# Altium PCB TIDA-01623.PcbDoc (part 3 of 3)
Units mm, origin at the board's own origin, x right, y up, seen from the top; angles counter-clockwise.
Board outline 77.73 x 42 mm, 4 copper layers (Top Layer, Signal Layer 1, Signal Layer 2, Bottom Layer), stack 0.651 mm thick; 213 components, 127 nets, 575 pads, 342 vias.
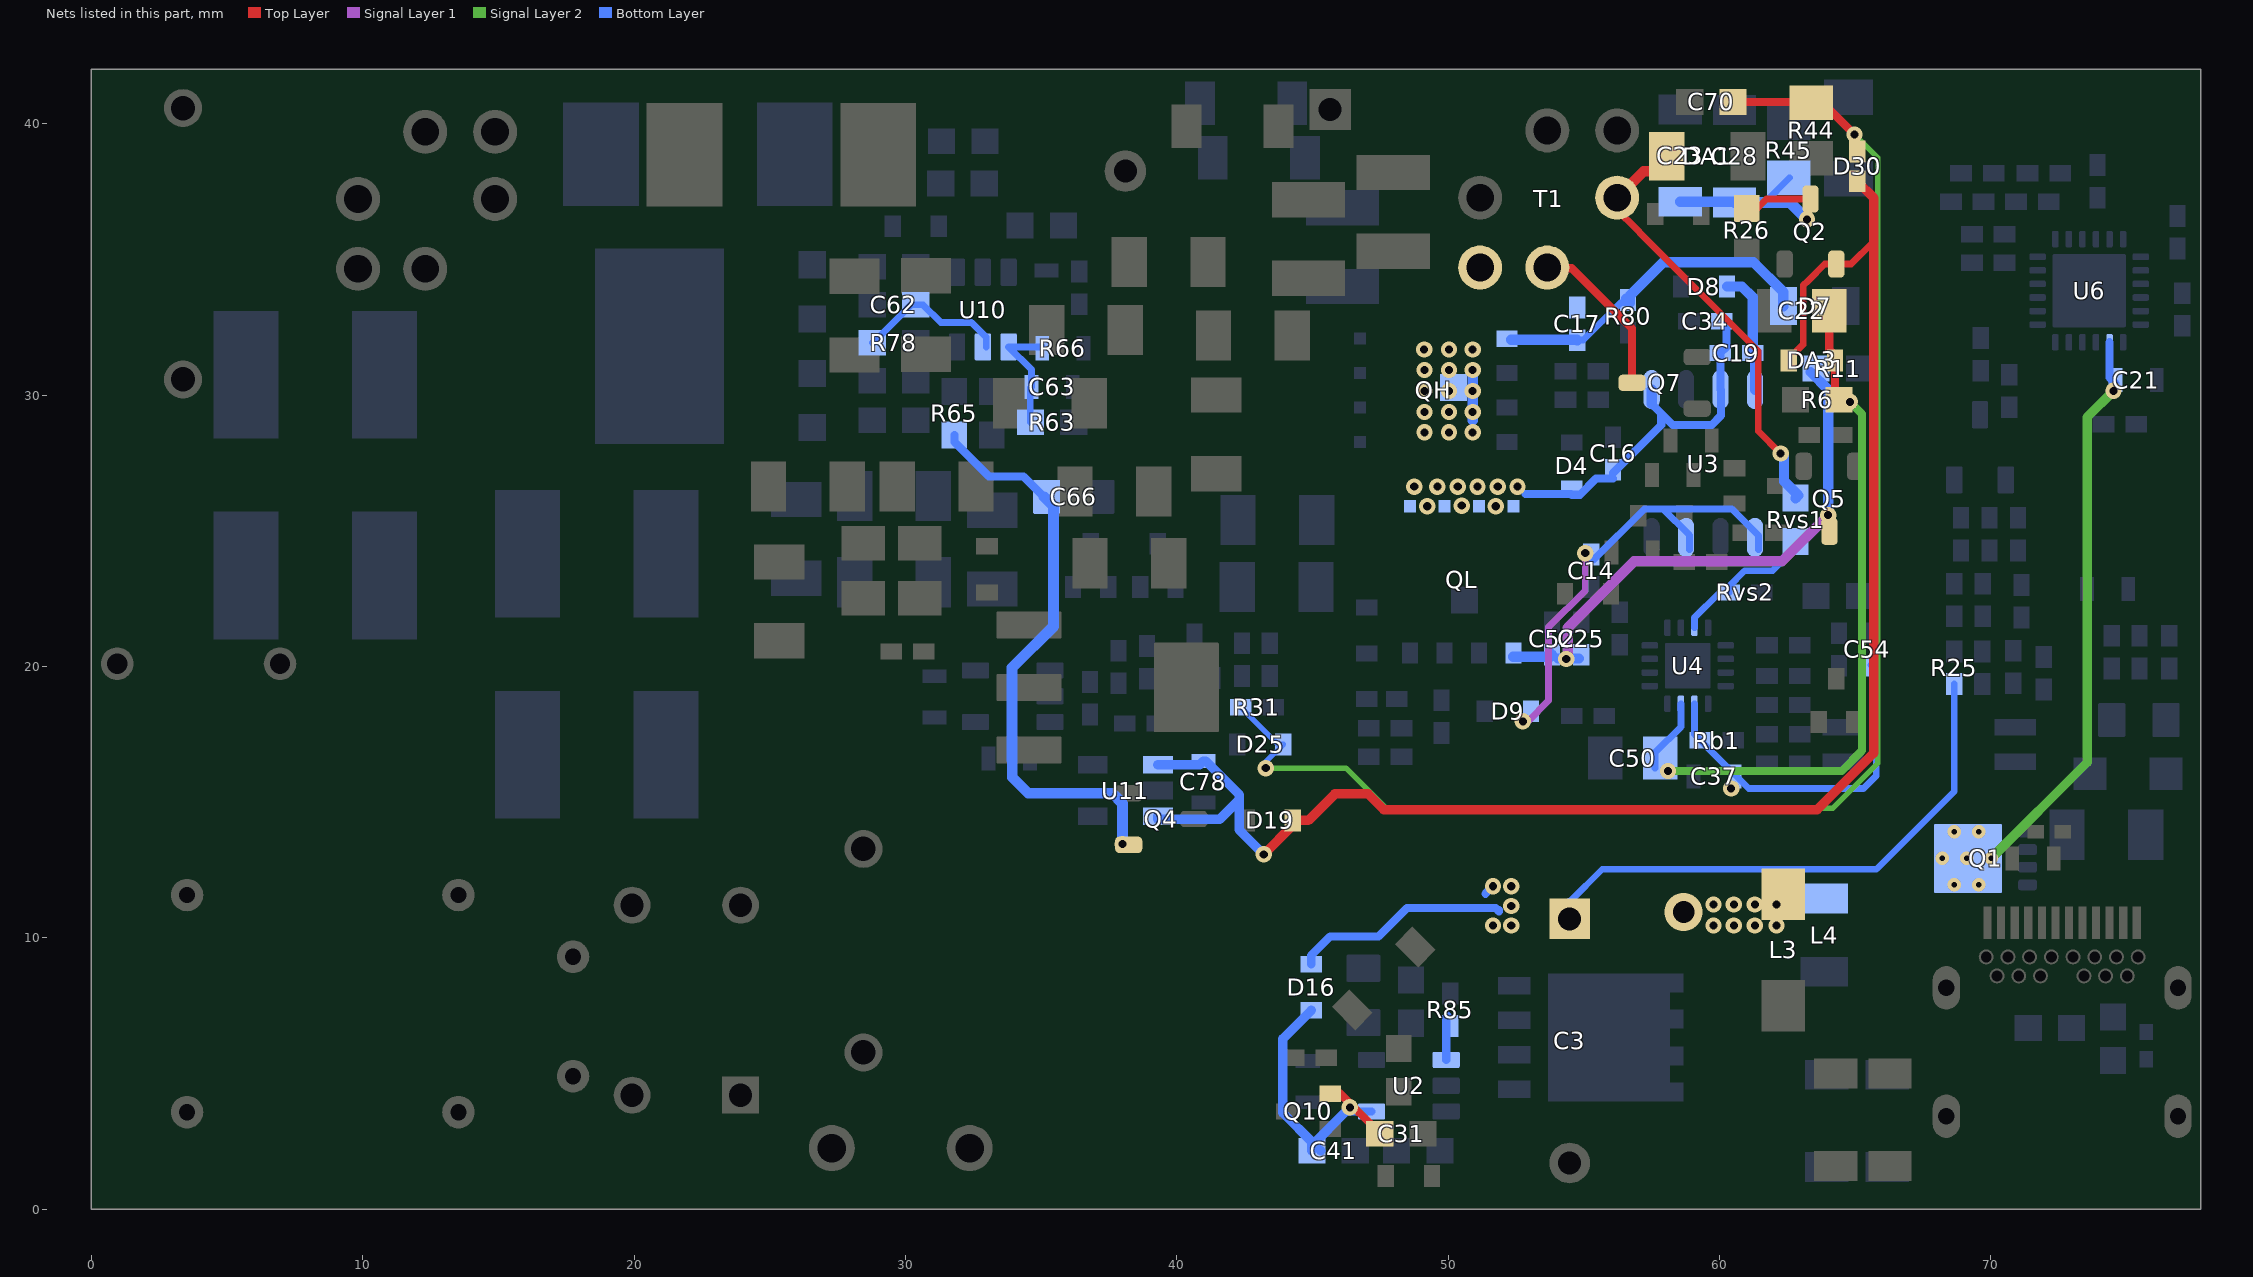
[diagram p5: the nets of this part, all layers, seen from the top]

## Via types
v1: diameter 0.6, hole 0.3, Top Layer to Bottom Layer, 299 vias
v2: diameter 0.635, hole 0.33, Top Layer to Bottom Layer, 15 vias
v3: diameter 0.5, hole 0.2, Top Layer to Bottom Layer, 12 vias
v4: diameter 0.61, hole 0.305, Top Layer to Bottom Layer, 5 vias
v5: diameter 1, hole 0.6, Top Layer to Bottom Layer, 2 vias
v6: diameter 2.4, hole 1.8, Top Layer to Bottom Layer, 2 vias
v7: diameter 1.2, hole 0.8, Top Layer to Bottom Layer, 2 vias
v8: diameter 1.4, hole 0.8, Top Layer to Bottom Layer, 2 vias
v9: diameter 2, hole 1.6, Top Layer to Bottom Layer, 1 vias
v10: diameter 1.9, hole 1.5, Top Layer to Bottom Layer, 1 vias
v11: diameter 0.6/0.6/0.6/0.6 (per signal layer), hole 0.3, Top Layer to Bottom Layer, 1 vias

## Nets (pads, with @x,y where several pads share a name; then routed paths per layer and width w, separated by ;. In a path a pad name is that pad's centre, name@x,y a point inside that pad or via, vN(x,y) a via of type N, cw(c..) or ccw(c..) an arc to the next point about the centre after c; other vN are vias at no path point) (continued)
VCC1: C14.1 D9.2 U3.1 U3.3 | length 17.4
  Signal Layer 1 w0.254: v1(52.75,17.975) 52.933,17.975 53.7,18.742 53.7,21.45 55.05,22.8 v1(55.05,24.175)
  Bottom Layer w0.254: v1(55.05,24.175) 55.074,24.175 55.337,23.912 57.227,25.802 57.923,25.802 58.89,24.835 U3.3@58.89,24.3 ; 57.925,25.8 59.773,25.8 59.775,25.802 60.295,25.802 60.297,25.8 60.45,25.8 61.43,24.82 U3.1@61.43,24.3
VCC2: C19.1 D8.2 U3.8 | length 4.5
  Bottom Layer w0.381: D8.2@60.275,34 60.825,34 61.222,33.603 C19.1@61.222,31.549 61.305,31.466 U3.8@61.305,30.2
VCC_PFC: C66.1 Q4.2 R65.2 | length 22
  Top Layer w0.3: v1(38,13.45) 38.475,13.45 Q4.2@38.5,13.425
  Bottom Layer w0.3: R65.2@31.8,28.525 31.8,28.275 33.075,27 34.35,27 C66.1@35.1,26.25
  Bottom Layer w0.4: C66.1@35.1,26.25 35.45,25.9 35.45,21.475 33.925,19.95 33.925,16.547 33.933,16.539 33.933,15.917 34.525,15.325 37.625,15.325 38,14.95 v1(38,13.45)
VCCH: C17.1 D7.1 QH.1 R80.2 | length 12.6
  Bottom Layer w0.25: C17.1@54.75,32.025 54.975,32.025 56.35,33.4 R80.2@56.7,33.4
  Bottom Layer w0.381: QH.1@52.328,32.038 54.737,32.038 C17.1@54.75,32.025 ; R80.2@56.55,33.55 56.613,33.488 56.7,33.4 56.7,33.675 57.925,34.9 61.25,34.9 62.35,33.8 D7.1@62.35,33.275
VCCL: C25.1 C52.1 Q5.3 QL.1 R11.2 | length 20.2
  Signal Layer 1 w0.381: v1@54.4,20.3 54.4,21.418 55.567,22.586 55.567,22.592 56.85,23.875 62.3,23.875 v1(64,25.575)
  Bottom Layer w0.381: QL.1@52.394,20.362 C52.1@53.762,20.362 ; C52.1@53.763,20.487 C52.1@53.825,20.425 ; C52.1@54.05,20.294 C25.1@54.819,20.294 ; R11.2@63.35,30.85 64,30.2 v1(64,25.575)
  other v1: 54.35,20.275
VDD: C22.1 C50.1 DA3.1 R6.1 U4.15 | length 26.1
  Top Layer w0.3: C22.1@64.041,33.125 64.041,31.684 DA3.1@64.325,31.4 ; DA3.1@64.25,31.325 64.25,29.975 R6.1@64.4,29.825
  Signal Layer 2 w0.3: v1@58.375,16.15 64.5,16.15 65.25,16.9 65.25,29.3 v1@64.975,29.575
  Bottom Layer w0.25: C50.1@57.625,16.25 57.625,16.825 58.575,17.775 U4.15@58.575,18.625
  other v1: 58.1,16.15 64.8,29.75
VDD1: C23.1 C28.1 Q2.3 R26.2 R45.1 | length 9
  Top Layer w0.25: R26.2@61.375,36.875 61.725,37.225 63.2,37.225 63.225,37.2 v1(63.225,36.475)
  Bottom Layer w0.25: C28.1@60.525,37.125 C28.1@60.55,37.1 ; 61.666,37.1 R45.1@62.575,38.009
  Bottom Layer w0.4: C23.1@58.55,37.125 C28.1@60.525,37.125 ; C28.1@60.55,37.1 61.666,37.1 62.6,37.1 v1(63.225,36.475)
VDD2: C70.1 D25.1 D30.2 R31.1 R44.1 | length 55.2
  Top Layer w0.3: C70.1@60.5,40.8 R44.1@63.341,40.8 ; R44.1@63.809,40.766 v1(64.975,39.6)
  Signal Layer 2 w0.2: v1(43.275,16.25) 46.225,16.25 47.7,14.775 64.175,14.775 65.825,16.425 65.825,38.75 v1(64.975,39.6)
  Bottom Layer w0.2: R31.1@42.35,18.5 43.725,17.125 D25.1@43.925,17.125 43.275,16.475 v1(43.275,16.25)
VDD3: C78.2 D19.2 D30.1 DA3.2 Q2.2 U11.1 U11.3 | length 61.5
  Top Layer w0.25: DA3.2@62.55,31.325 63.081,31.856 63.081,34.035 63.271,34.225 63.275,34.225 63.875,34.825 Q2.2@64.15,34.825 ; Q2.2@64.3,34.825 64.85,34.825 65.675,35.65
  Top Layer w0.35: v1(43.2,13.075) 44.275,14.15 D19.2@44.275,14.325 44.85,14.325 45.825,15.3 47.054,15.3 47.625,14.729 47.625,14.725 63.6,14.725 65.675,16.8 65.675,35.65 65.675,37.275 D30.1@65.075,37.875
  Bottom Layer w0.35: U11.3@39.3,14.475 39.3,14.359 41.575,14.359 42.291,15.075 42.3,15.075 ; U11.1@39.3,16.375 40.838,16.375 C78.2@40.975,16.512 41.063,16.512 42.3,15.275 42.3,15.075 ; v1(43.2,13.075) 42.3,13.975 42.3,15.075
VDDS: C31.1 C41.2 D16.1 Q10.2 U2.4 | length 11.8
  Top Layer w0.3: Q10.2@45.65,4.25 46.025,4.25 47.475,2.8 C31.1@47.475,2.775
  Bottom Layer w0.3: v1@46.225,3.6 U2.4@47.175,3.6
  Bottom Layer w0.35: D16.1@44.95,7.325 43.9,6.275 43.9,3.55 45.037,2.412 45.137,2.312 C41.2@45.3,2.15 ; C41.2@44.975,2.15 44.975,2.35 46.225,3.6 v1(46.375,3.75)
VG: R85.2 U2.1 | length 1.6
  Bottom Layer w0.3: U2.1@49.925,5.5 49.925,7.075 R85.2@49.975,7.125
VO: C3.1 C21.1 D16.2 L3.2 L4.2 Q1.5 Q1.6 Q1.7 Q1.8 Q1.9@69.155,12.925 R25.2 U6.20 | length 49.2
  Signal Layer 2 w0.25: v1@74.354,30.154 v1(74.517,30.154)
  Signal Layer 2 w0.35: v3(70.008,12.925) 73.55,16.468 73.55,29.187 v1(74.517,30.154)
  Bottom Layer w0.25: C3.1@54.45,11.35 54.5,11.35 55.675,12.525 65.534,12.525 65.775,12.525 68.65,15.4 R25.2@68.65,19.35
  Bottom Layer w0.3: D16.2@44.95,9.025 44.95,9.35 45.65,10.05 47.425,10.05 48.475,11.1 51.75,11.1 51.875,10.975 51.875,11.025 ; 51.375,11.625 v1(51.65,11.9) ; U6.20@74.37,31.945 74.37,30.645 C21.1@74.583,30.432
  other v1: 51.65,10.45 52.325,10.45 59.775,10.45 60.525,10.45 61.3,10.45 62.1,10.45 52.325,11.175 59.775,11.225 60.525,11.225 61.3,11.225 62.1,11.225 52.325,11.9
  other v3: 68.65,11.95 69.555,11.95 68.198,12.925 69.103,12.925 68.65,13.9 69.555,13.9
  other v8: 58.675,10.95
VOSNS: C63.2 R63.1 R66.2 U10.1 | length 4.4
  Bottom Layer w0.25: R63.1@34.6,29 34.6,30.262 C63.2@34.638,30.3 34.638,30.937 U10.1@33.8,31.775 R66.2@35.038,31.775
VREF: C37.1 C54.1 Rb1.2 U4.14 | length 13
  Bottom Layer w0.25: U4.14@59.075,18.625 59.075,17.5 Rb1.2@59.3,17.275 61.075,15.5 65.3,15.5 65.775,15.975 65.775,19.85 C54.1@65.575,20.05
  other v1: 60.425,15.5
VS: Rvs1.1 Rvs2.2 U4.7 | length 5
  Bottom Layer w0.25: U4.7@59.075,21.425 59.075,21.8 59.95,22.675 ; Rvs2.2@60.35,22.725 60.35,22.95 60.925,23.525 61.95,23.525 Rvs1.1@62.875,24.45
VSV: DA1.2 Rvs1.2 T1.3 | length 16.4
  Top Layer w0.25: T1.3@56.225,37.275 56.225,36.825 56.935,36.115 56.935,36.113 57.163,35.884 57.166,35.884 61.425,31.625 61.425,28.675 v1(62.25,27.85)
  Top Layer w0.381: T1.3@56.225,37.275 57.2,38.25 DA1.2@58.3,38.25
  Bottom Layer w0.381: v1(62.25,27.85) 62.375,27.725 62.375,26.825 62.9,26.3 Rvs1.2@62.8,26.2
VSW: C16.2 C17.2 C19.2 C34.1 D4.2 Q7.3 QH.9 QL.5 QL.6 QL.7 QL.8 T1.4 T1.5 U3.5 U3.7 | length 21.4
  Top Layer w0.3: T1.4@53.625,34.675 54.55,34.675 56.775,32.45 Q7.3@56.775,30.375
  Bottom Layer w0.3: 52.85,26.35 54.525,26.35 54.55,26.325 54.85,26.325 55.45,26.925 C16.2@56.075,26.925 ; C16.2@56.075,27.125 57.85,28.9 57.85,29.325 ; U3.5@57.495,29.68 57.85,29.325 ; C34.1@60.25,32.675 60.25,31.777 C19.2@60.022,31.549 60.035,31.536 U3.7@60.035,30.2 60.05,30.185 60.05,29.24 59.71,28.9 58.275,28.9 57.85,29.325
  Bottom Layer w0.381: v1@50.9,29.075 v1@50.9,30.8 ; U3.5@57.495,29.68 U3.5@57.495,30.2
  other v1: 49.225,25.9 51.75,25.9 50.5,25.925 48.75,26.625 49.6,26.625 50.35,26.625 51.075,26.625 51.825,26.625 52.55,26.625 49.125,28.625 50.025,28.625 50.9,28.625 49.125,29.375 50.025,29.375 50.9,29.375 49.125,30.15 50.025,30.15 50.9,30.15 49.125,30.925 50.025,30.925 50.9,30.925 49.111,31.675 50.025,31.675 50.9,31.675
ZCD: C62.2 R78.1 U10.2 | length 5.6
  Bottom Layer w0.25: R78.1@28.775,31.925 28.81,31.925 30.21,33.325 C62.2@30.375,33.325 30.65,33.325 31.3,32.675 32.425,32.675 32.979,32.121 U10.2@32.979,31.771
pads on no net: J2.A2 J2.A3 J2.A8 J2.A10 J2.A11 J2.B2 J2.B3 J2.B8 J2.B10 J2.B11 Q1.9@68.625,11.95 Q1.9@68.625,12.6 Q1.9@68.625,13.9 Q1.9@68.625,13.25 Q1.9@69.103,12.263 Q1.9@69.103,13.587 Q1.9@69.473,12.925 Q1.9@70.008,12.263 Q1.9@70.008,13.587 U4.17@58.825,20.025 U6.9 U6.10 U6.25@72.925,33.15 U6.25@72.925,34.54 U6.25@74.315,33.15 U6.25@74.315,34.54 U11.4

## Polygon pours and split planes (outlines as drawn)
SGND on Bottom Layer "Signal Layer 2-No Net 3" (solid, pour order 378): 68.151,9.676 76.949,9.676 77.575,9.05 77.575,0.575 77.25,0.25 67.825,0.25 66.25,0.25 65.5,1 65.5,7.025
390V_BUS on Bottom Layer "Bottom Layer-No Net 11" (solid, pour order 242): 43.6,41.625 49.925,41.625 50.75,40.8 50.75,39.05 50.75,39.025 52.05,37.725 52.025,37.7 52.025,36.825 51.725,36.525 48.225,36.525 47.9,36.2 46.675,36.2 43.925,36.2 43.475,36.65 43.475,41.5
DRAIN on Bottom Layer "Bottom Layer-No Net 9" (solid, pour order 230): 11.925,41.525 20.85,41.525 21.925,40.45 21.925,37.375 24.4,34.9 24.4,28.4 24.15,28.15 18.6,28.15 15.45,31.3 15.45,35.555 11.425,39.448 11.425,41.025
GDNS on Bottom Layer "Bottom Layer-No Net 7" (solid, pour order 184): 71.1,15.125 73.375,15.125 73.65,14.85 73.65,12.975 73.475,12.8 72.025,12.8 71.625,12.4 71,12.4 70.875,12.525 70.875,14.9
VO on Bottom Layer "Top Layer-No Net 2" (solid, pour order 182): 51.075,10.325 51.5,9.9 69.875,9.9 70.5,10.525 70.5,14.5 68.275,14.5 66,12.225 63.15,12.225 55.253,12.225 54.903,12.45 51.2,12.45 51.075,12.325
PGND on Bottom Layer "Bottom Layer-No Net 4" (solid, pour order 172): 43.3,21.9 43.3,27.3 42.3,28.3 42.3,40.75 41.425,41.625 39.875,41.625 36.925,41.625 36.1,40.8 36.1,38.8 38.6,36.3 38.6,26.475 40.8,24.275 40.8,22.2 41.1,21.9
F on Bottom Layer "Top Layer-No Net" (solid, pour order 158): 53.695,9.345 61.854,9.345 62.255,8.945 62.254,4.629 61.45,3.825 60.6,3.825 60.53,3.895 53.755,3.895 53.475,4.175 53.475,9.125
VBUS on Bottom Layer "Bottom Layer-No Net 2" (solid, pour order 150): 75.05,14.75 77.225,14.75 77.7,14.275 77.55,14.125 77.55,10.95 77.55,9.7 75.83,9.7 75.055,8.925 70.644,8.925 70.644,10.844 71.275,11.475 72.675,11.475 74.85,13.65 74.85,14.55
PGND1 on Bottom Layer "Bottom Layer-No Net 1" (solid, pour order 138): 43.6,26.6 46.825,26.6 46.825,24.9 47.875,23.85 54.325,23.85 55.6,22.575 55.6,21.575 55.2,21.175 44.575,21.175 43.6,22.15
SGND on Bottom Layer "Bottom Layer-No Net 5" (solid, pour order 176): 53.5,3.5 62.325,3.5 62.975,4.15 67.175,4.15 67.175,0.275 60.875,0.275 56.9,0.275 51.175,0.275 50.7,0.75 50.7,7.125 51.2,7.625 52.925,7.625 53.184,7.366 53.184,3.816
AC_R on Bottom Layer "Bottom Layer-No Net 14" (solid, pour order 268): 8.775,37.55 9.325,38.1 10.15,38.1 13.337,34.913 13.337,30.72 17.6,26.178 17.6,21.875 17.275,21.55 14.875,21.55 14.65,21.775 14.65,26.1 12.575,28.175 9.675,28.175 9.4,28.45 9.4,34.05 8.775,34.675
VSW on Bottom Layer "Bottom Layer-No Net" (solid, pour order 110): 55.154,35.5 55.725,34.979 55.725,33.425 55.05,32.75 51.65,32.75 51.45,32.55 51.45,27.8 51.55,27.7 56.4,27.7 56.6,27.5 56.6,26.925 55.35,25.675 54.575,25.675 53.95,25.05 48.25,25.05 47.925,25.375 47.925,27.125 48.5,27.7 48.5,31.925 49.4,32.825 49.4,34.825 50.075,35.5
NetC42_1 on Bottom Layer "Bottom Layer-No Net 3" (solid, pour order 170): 47.075,27.75 47.3,27.975 47.3,32.325 48.3,33.325 48.3,35.375 48.05,35.625 43.7,35.625 43.45,35.375 43.45,29.025 44.725,27.75
390V_BUS on Bottom Layer "Bottom Layer-No Net 12" (solid, pour order 306): 24.15,41.4 28.175,41.4 28.175,38.1 26.875,36.8 24.575,36.8 23.925,37.45 23.925,41.175
SGND on Bottom Layer "Bottom Layer-No Net 16" (solid, pour order 316): 74.025,18.95 74.8,18.95 74.8,18.925 75.025,18.7 75.025,15.875 74.575,15.425 74.1,15.425 72.925,15.425 72.8,15.55 72.825,15.575 72.825,16.55 72.825,16.6 73.1,16.875 73.675,17.45 73.675,17.625 73.675,18.6
PGND on Bottom Layer "Bottom Layer-No Net 17" (solid, pour order 318): 58,19.45 56.225,19.45 56.05,19.45 55.225,18.625 55.2,18.6 55.2,17.625 55.075,17.5 54.175,17.5 53.85,17.175 53.85,15.408 54.386,15 59.625,15 59.8,15.175 59.8,16.25 59.5,16.55 58.85,16.55 58.825,16.55 58.625,16.35 58.1,15.825 57,15.825 57,17.675 58,17.675 58.375,18.05 58.375,19.325 58.25,19.45 58.2,19.5 58.05,19.5
S on Bottom Layer "Bottom Layer-No Net 15" (solid, pour order 320): 63,9.475 66.9,9.475 67.35,9.025 67.35,4.7 66.975,4.325 66.825,4.325 63.025,4.325 62.875,4.475 62.875,5.775 62.875,9.35
PGND on Bottom Layer "Top Layer-No Net 8" (solid, pour order 322): 0.75,33.725 6.475,33.725 7.025,33.175 7.025,28.4 6.725,28.1 0.875,28.1 0.35,28.625 0.35,33.325
NetBD1_2 on Bottom Layer "Bottom Layer-No Net 13" (solid, pour order 324): 4.45,25.825 11.625,25.825 11.9,25.825 12.125,25.6 12.125,20.175 11.375,19.425 5.5,19.425 4.875,19.425 4.325,19.975 4.325,25.7
NetBD2_2 on Bottom Layer "Bottom Layer-No Net 18" (solid, pour order 326): 14.9,19.3 22.25,19.3 22.475,19.3 22.725,19.05 22.725,14.65 22.425,14.35 17.15,14.35 13.725,10.925 12.35,10.925 12.1,10.925 11.45,11.575 11.45,14.825 11.45,15.475 14.7,18.725 14.7,19.1
AC_R on Bottom Layer "Bottom Layer-No Net 19" (solid, pour order 336): 1,41.7 0.325,41.025 0.325,37.55 1.6,36.275 6.95,36.275 9.5,33.725 10.775,33.725 12.65,35.6 9.05,39.2 9.05,41.35 8.7,41.7
PGND on Bottom Layer "Bottom Layer-No Net 20" (solid, pour order 348): 20,26.525 22.35,26.525 22.425,26.45 22.425,21.825 22.375,21.775 20,21.775 19.925,21.85 19.925,26.45 20,26.525
NetC57_2 on Bottom Layer "Bottom Layer-No Net 21" (solid, pour order 358): 26.025,33.3 27.675,33.3 27.85,33.125 27.85,31.375 28.2,31.025 29.25,31.025 29.35,30.925 29.35,28.525 29.125,28.3 26.325,28.3 26.075,28.3 25.95,28.425 25.95,33.225
PGND on Bottom Layer "Bottom Layer-No Net 13" (solid, pour order 366): 29.8,35.425 32,35.425 32.25,35.125 32.25,34.125 32.25,34.075 32.425,33.9 37.4,33.9 37.725,33.575 37.725,25.6 37.3,25.175 32.7,25.175 32.7,28.2 36.903,28.2 37.025,28.322 37.025,29.459 36.707,29.776 35.926,29.776 35.693,30.009 35.693,32.307 35.55,32.45 33.3,32.45 32.65,33.1 31.775,33.1 31.75,33.1 31.475,33.375 31.275,33.575 31.275,34.15 31.2,34.225 29.8,34.225
SGND on Top Layer "Signal Layer 2-No Net 3" (solid, pour order 376): 67.4,11.275 77.325,11.275 77.575,11.025 77.575,0.575 77.25,0.25 67.825,0.25 65.777,0.25 65.5,0.527 65.5,9.375
PGND on Top Layer "Top Layer-No Net 4" (solid, pour order 250): 36.6,41.625 40.575,41.625 40.675,41.625 41.175,41.125 41.2,41.1 41.2,38.025 41.2,37.95 40.925,37.675 40.775,37.525 36.4,37.525 32.525,33.65 27.075,33.65 26.825,33.9 26.825,35.4 27.1,35.675 31.125,35.675 32.45,37 32.45,40.9 33.175,41.625
390V_BUS on Top Layer "Bottom Layer-No Net 12" (solid, pour order 248): 26.2,41.65 30.4,41.65 30.4,37.35 29.975,36.925 26.225,36.925 25.975,37.175 25.975,41.425
390V_BUS on Top Layer "Bottom Layer-No Net 11" (solid, pour order 244): 44,41.625 49.925,41.625 50.75,40.8 50.75,39.05 50.75,39.025 52.05,37.725 52.025,37.7 52.025,36.85 51.65,36.475 51.625,36.45 50.575,36.45 50.3,36.45 49.7,37.05 46.7,37.05 46.2,36.55 43.475,36.55 43.25,36.775 43.25,40.875
SGND on Top Layer "Bottom Layer-No Net 5" (solid, pour order 178): 49.125,4.175 52.425,4.175 53.225,3.375 61.636,3.375 65.925,3.375 65.925,0.675 65.475,0.225 48.95,0.225 48.55,0.625 48.55,3.6
VO on Top Layer "Top Layer-No Net 2" (solid, pour order 166): 51.325,9.875 52,9.2 68.439,9.2 70.25,12 70.25,14.175 67.375,14.175 65.825,12.625 51.925,12.625 51.325,12.025
S on Top Layer "Top Layer-No Net 1" (solid, pour order 164): 63.35,3.575 66.775,3.575 67.525,4.325 67.525,7.825 66.575,8.775 61.775,8.775 61.5,8.5 61.5,6.6 62.875,5.225 62.875,4.05
F on Top Layer "Top Layer-No Net" (solid, pour order 156): 50.25,8.9 60.975,8.9 61.175,8.7 61.175,6.4 62.1,5.475 62.1,4.425 61.45,3.775 53.525,3.775 52.725,4.575 50.431,4.575 49.875,5.131 49.875,8.525
SGND on Top Layer "Signal Layer 2-No Net 2" (solid, pour order 154): 76.2,38.725 77.725,37.2 77.725,12.45 70.65,12.45 68.275,14.825 68.275,36.6 70.4,38.725
NetC42_1 on Top Layer "Bottom Layer-No Net 3" (solid, pour order 192): 46.85,27.95 47.3,28.4 47.3,32.625 49.325,34.65 49.325,35.875 49.25,35.95 43.675,35.95 43.425,35.7 43.425,28.35 43.825,27.95
NetC57_2 on Top Layer "Top Layer-No Net 5" (solid, pour order 270): 26.125,32.225 31.825,32.225 31.96,32.09 31.96,29.66 31.125,28.825 26.25,28.825 26.125,28.95
PGND on Top Layer "Top Layer-No Net 6" (solid, pour order 276): 41.85,25.025 42.9,25.025 43.075,24.85 43.075,22.975 42.8,22.7 42.025,22.7 41.7,23.025 41.7,24.875
VSW on Top Layer "Bottom Layer-No Net" (solid, pour order 280): 54.225,35.5 55.175,34.55 55.175,29.225 55.175,25.85 54.35,25.025 48.25,25.025 47.925,25.35 47.925,27.1 48.675,27.85 48.675,32.225 50.325,33.875 50.325,35 50.825,35.5
PGND on Top Layer "Signal Layer 2-No Net" (solid, pour order 284): 60.133,15.25 60.958,15.925 62.45,15.925 63.05,16.525 63.05,21.493 60.556,21.493 54.381,21.493 53.456,20.568 44.225,20.568 44.225,15.25
PGND1 on Top Layer "Bottom Layer-No Net 1" (solid, pour order 310): 43.45,26.6 46.825,26.6 46.825,24.9 47.875,23.85 53.175,23.85 53.65,23.375 53.75,23.275 53.75,21.875 53.275,21.4 44.25,21.4 43.45,22.2
PGND on Top Layer "Top Layer-No Net 8" (solid, pour order 328): 0.75,33.725 6.475,33.725 7.025,33.175 7.025,28.4 6.725,28.1 0.875,28.1 0.35,28.625 0.35,33.325
NetBD1_2 on Top Layer "Bottom Layer-No Net 13" (solid, pour order 330): 4.45,25.825 11.625,25.825 11.9,25.825 12.125,25.6 12.125,20.175 11.375,19.425 5.5,19.425 4.875,19.425 4.325,19.975 4.325,25.7
AC_R on Top Layer "Bottom Layer-No Net 10" (solid, pour order 234): 13,35.025 16.425,35.025 18.075,36.675 18.075,41.6 23,41.6 23.625,41.6 23.625,29.775 22.125,28.275 19.7,28.275 16.55,25.125 15.625,25.125 13.15,27.6 13.15,30.045 13,30.239
NetBD2_2 on Top Layer "Bottom Layer-No Net 18" (solid, pour order 338): 14.9,19.3 21.1,19.3 22.725,17.675 22.725,14.725 22.4,14.4 17.2,14.4 13.775,10.975 12.05,10.975 11.45,11.575 11.45,14.825 11.45,15.475 14.7,18.725 14.7,19.1
AC_R on Top Layer "Bottom Layer-No Net 14" (solid, pour order 340): 9.4,38.1 10.15,38.1 13.337,34.913 13.337,30.72 17.6,26.178 17.6,21.875 17.275,21.55 14.875,21.55 14.65,21.775 14.65,26.1 12.575,28.175 9.975,28.175 9.4,28.75 9.4,35.55
AC_R on Top Layer "Bottom Layer-No Net 19" (solid, pour order 342): 1,41.7 0.325,41.025 0.325,37.375 1.325,36.375 6.775,36.375 9.425,33.725 10.025,33.725 12.275,35.975 9.05,39.2 9.05,40.5 7.85,41.7
PGND on Top Layer "Bottom Layer-No Net 20" (solid, pour order 350): 20.325,26.525 22.35,26.525 22.425,26.45 22.425,21.825 22.375,21.775 20,21.775 19.925,21.85 19.925,26.125
SGND on Signal Layer 2 "Signal Layer 2-No Net 3" (solid, pour order 374): 68.55,10.375 77.025,10.375 77.15,10.375 77.55,9.975 77.575,9.95 77.575,0.575 77.25,0.25 67.825,0.25 66.25,0.25 65.125,1.375 65.125,6.95
SGND on Signal Layer 2 "Signal Layer 1-No Net" (solid, pour order 372): 42.95,0.35 67.175,0.35 67.175,2.025 54.5,2.025 52.375,4.15 51.378,4.15 49.575,5.953 49.575,9.725 43.875,9.725 42.275,8.125 42.275,1.025
SGND on Signal Layer 2 "Signal Layer 2-No Net 2" (solid, pour order 302): 77.3,39.475 77.725,39.05 77.725,10.725 68.35,10.725 65.771,8.146 64.85,6.306 64.85,2.725 64.475,2.35 59.866,2.35 56.025,2.35 54.25,2.35 55.325,3.425 61.969,3.425 62.675,4.131 62.675,12.725 65.925,12.725 67.95,14.75 67.95,38.1 69.325,39.475
F on Signal Layer 2 "Top Layer-No Net" (solid, pour order 298): 50.85,9.525 61.7,9.525 62.175,9.05 62.175,4.075 61.8,3.7 52.25,3.7 50.65,5.3 49.9,6.05 49.9,8.575
VO on Signal Layer 2 "Top Layer-No Net 2" (solid, pour order 294): 50.125,10.1 50.3,9.925 62.425,9.925 62.425,12.675 50.475,12.675 50.125,12.325
PGND on Signal Layer 2 "Signal Layer 2-No Net" (solid, remove dead copper, pour order 108): 65.65,21 65.65,41.6 56.25,41.6 56.25,36.425 58.65,34.025 58.65,27.565 56.65,25.565 56.65,24.989 52.31,21.225 45.128,21.225 44.189,21.8 40.625,21.8 40.625,15.25 62.2,15.25 63.425,16.475 63.425,19.725 62.8,20.35 59.6,20.35 59.6,21 63.25,21
NetC42_1 on Signal Layer 2 "Bottom Layer-No Net 3" (solid, pour order 188): 47,27.75 47.3,28.05 47.3,32.15 49.2,34.05 49.2,35.85 48.975,36.075 43.775,36.075 43.525,35.825 43.525,29.875 44.55,28.85 44.55,28.05 44.85,27.75
VSW on Signal Layer 2 "Bottom Layer-No Net" (solid, pour order 200): 54.7,35.575 55.325,34.95 55.325,26.75 53.625,25.05 48.25,25.05 47.925,25.375 47.925,27.125 48.675,27.875 48.675,32.25 50.225,33.8 50.225,35.125 50.675,35.575
PGND on Signal Layer 2 "Bottom Layer-No Net 4" (solid, pour order 256): 43.3,22.4 43.8,22.9 43.8,28.425 42.875,29.35 42.875,37.475 41.35,39 37.925,39 37.45,38.525 37.45,37.6 40.3,34.75 40.3,23.125 41.025,22.4
390V_BUS on Signal Layer 2 "Bottom Layer-No Net 11" (solid, pour order 260): 43.975,41.625 49.9,41.625 50.725,40.8 50.725,39.05 50.725,39.025 52.025,37.725 52,37.7 52,36.85 51.625,36.475 51.6,36.45 49.925,36.45 49.525,36.85 45.05,36.85 43.45,38.45 43.45,41.1
PGND on Signal Layer 2 "Signal Layer 1-No Net 1" (solid, pour order 272): 16.95,27.45 19.925,24.475 19.925,21.975 20.1,21.8 26.425,21.8 31.25,16.975 39.825,16.975 39.825,34.6 35.425,39 33.025,39 29.459,35.175 16.35,35.175 14.175,33 0.6,33 0.275,32.675 0.275,27.45
390V_BUS on Signal Layer 2 "Bottom Layer-No Net 12" (solid, pour order 304): 26.325,41.775 30.4,41.775 30.4,38.525 28.925,37.05 26.175,37.05 26.1,37.05 25.5,37.65 25.5,40.95
PGND1 on Signal Layer 2 "Bottom Layer-No Net 1" (solid, pour order 312): 44.075,26.725 46.825,26.725 46.825,24.9 47.875,23.85 53.55,23.85 53.75,23.65 53.75,21.875 53.075,21.2 45.725,21.2 44.075,22.85
NetBD1_2 on Signal Layer 2 "Bottom Layer-No Net 13" (solid, pour order 334): 4.45,25.825 11.625,25.825 11.9,25.825 12.125,25.6 12.125,20.175 11.375,19.425 5.5,19.425 4.875,19.425 4.325,19.975 4.325,25.7
NetBD2_2 on Signal Layer 2 "Bottom Layer-No Net 18" (solid, pour order 346): 14.9,19.3 22.25,19.3 22.475,19.3 22.725,19.05 22.725,14.725 22.4,14.4 17.2,14.4 13.725,10.925 12.35,10.925 12.1,10.925 11.45,11.575 11.45,14.825 11.45,15.475 14.7,18.725 14.7,19.1
AC_R on Signal Layer 2 "Bottom Layer-No Net 19" (solid, pour order 356): 1,41.7 0.325,41.025 0.325,37.325 1.275,36.375 6.825,36.375 9.35,33.85 12.675,33.85 13.15,34.325 13.15,35.975 7.475,41.65
AC_R on Signal Layer 2 "Signal Layer 2-No Net 1" (solid, pour order 364): 15,25.825 17.175,25.825 17.525,25.475 17.525,21.925 17.375,21.775 14.9,21.775 14.875,21.775 14.7,21.95 14.7,25.525 15,25.825
390V_BUS on Signal Layer 1 "Bottom Layer-No Net 11" (solid, pour order 370): 43.975,41.625 49.9,41.625 50.725,40.8 50.725,39.05 50.725,39.025 52.025,37.725 52,37.7 52,36.85 51.625,36.475 51.6,36.45 49.925,36.45 49.525,36.85 45.05,36.85 43.45,38.45 43.45,41.1
NetC42_1 on Signal Layer 1 "Bottom Layer-No Net 3" (solid, pour order 368): 47,27.75 47.3,28.05 47.3,32.15 49.2,34.05 49.2,35.85 48.975,36.075 43.775,36.075 43.525,35.825 43.525,29.875 44.55,28.85 44.55,28.05 44.85,27.75
VO on Signal Layer 1 "Top Layer-No Net 2" (solid, pour order 290): 50.075,10.15 50.3,9.925 62.65,9.925 62.65,12.675 50.25,12.675 50.075,12.5
PGND on Signal Layer 1 "Signal Layer 1-No Net 1" (solid, pour order 236): 19.6,34.025 19.6,22.175 20,21.775 26.35,21.775 31.4,16.725 39.95,16.725 39.95,34.475 35.425,39 33.024,39 29.459,35.175 20.75,35.175
SGND on Signal Layer 1 "Signal Layer 1-No Net" (solid, pour order 186): 42.95,0.35 64.825,0.35 64.825,3.125 53.4,3.125 52.375,4.15 51.378,4.15 49.575,5.953 49.575,9.725 44.775,9.725 42.275,7.225 42.275,1.025
F on Signal Layer 1 "Top Layer-No Net" (solid, pour order 160): 50.85,9.525 61.2,9.525 62.175,8.55 62.175,4.075 61.5,3.4 58.725,3.4 52.55,3.4 50.65,5.3 49.9,6.05 49.9,8.575
VSW on Signal Layer 1 "Bottom Layer-No Net" (solid, pour order 202): 52.075,35.575 52.45,35.2 52.45,33.7 51.25,32.5 51.25,27.8 51.8,27.25 52.725,27.25 52.75,27.25 53.325,26.675 53.325,25.425 52.95,25.05 48.25,25.05 47.925,25.375 47.925,27.125 48.675,27.875 48.675,32.25 50.225,33.8 50.225,35.125 50.675,35.575
390V_BUS on Signal Layer 1 "Bottom Layer-No Net 12" (solid, pour order 254): 25.575,41.6 30.075,41.6 30.525,41.15 30.55,41.125 30.55,38.35 29.125,36.925 25.55,36.925 25.05,37.425 25.05,41.075
PGND on Signal Layer 1 "Bottom Layer-No Net 4" (solid, pour order 264): 42.975,22.35 43.775,23.15 43.775,28.45 42.825,29.4 42.825,37.8 41.625,39 36.9,39 36.6,38.7 36.6,38.45 40.475,34.575 40.475,22.975 41.1,22.35
VSW on Signal Layer 1 "Bottom Layer-No Net" (solid, pour order 278): 54.775,35.55 55.275,35.05 55.275,26.725 53.575,25.025 48.25,25.025 47.925,25.35 47.925,27.1 48.675,27.85 48.675,32.225 50.225,33.775 50.225,35.1 50.675,35.55
PGND on Signal Layer 1 "Signal Layer 2-No Net" (solid, pour order 282): 63.8,16.325 63.6,16.525 63.6,17.4 65.75,17.4 65.75,41.6 56.167,41.6 56,41.433 56,36.425 58.9,33.525 58.9,25.725 54.025,20.85 42.975,20.85 42.975,19.6 48.075,14.5 64.775,14.5 65.75,15.475 65.75,16.983 65.133,16.983 64.475,16.325
PGND1 on Signal Layer 1 "Bottom Layer-No Net 1" (solid, pour order 314): 44,26.725 46.825,26.725 46.825,24.9 47.875,23.85 53.225,23.85 53.75,23.325 53.75,21.875 53.05,21.175 44.475,21.175 44,21.65
NetBD1_2 on Signal Layer 1 "Bottom Layer-No Net 13" (solid, pour order 332): 4.45,25.825 11.625,25.825 11.9,25.825 12.125,25.6 12.125,20.175 11.375,19.425 5.5,19.425 4.875,19.425 4.325,19.975 4.325,25.7
NetBD2_2 on Signal Layer 1 "Bottom Layer-No Net 18" (solid, pour order 344): 14.9,19.3 22.25,19.3 22.475,19.3 22.725,19.05 22.725,14.725 22.4,14.4 17.2,14.4 13.725,10.925 12.35,10.925 12.1,10.925 11.45,11.575 11.45,14.825 11.45,15.475 14.7,18.725 14.7,19.1
PGND on Signal Layer 1 "Bottom Layer-No Net 20" (solid, pour order 352): 20,26.525 22.35,26.525 22.425,26.45 22.425,21.825 22.375,21.775 20,21.775 19.925,21.85 19.925,26.45 20,26.525
AC_R on Signal Layer 1 "Bottom Layer-No Net 19" (solid, pour order 354): 1,41.7 0.325,41.025 0.325,37.425 1.325,36.425 6.425,36.425 9.375,33.475 11.3,33.475 13.037,35.212 9.05,39.2 9.05,40.5 7.85,41.7
AC_R on Signal Layer 1 "Bottom Layer-No Net 14" (solid, pour order 360): 8.75,37.525 9.325,38.1 10.15,38.1 13.337,34.913 17.6,30.65 17.6,21.875 17.275,21.55 14.875,21.55 14.65,21.775 14.65,26.1 12.575,28.175 9.675,28.175 9.4,28.45 9.4,33.45 8.75,34.1
PGND on Signal Layer 1 "Top Layer-No Net 8" (solid, pour order 362): 0.75,33.725 6.475,33.725 7.025,33.175 7.025,28.4 6.725,28.1 0.875,28.1 0.35,28.625 0.35,33.325
SGND on Signal Layer 1 "Signal Layer 2-No Net 2" (solid, pour order 380): 76.2,38.725 77.725,37.2 77.725,11.05 72.6,11.05 68.275,15.375 68.275,36.6 70.4,38.725
SGND on Signal Layer 1 "Signal Layer 2-No Net 3" (solid, pour order 382): 63.612,9.412 69.163,9.412 70.175,10.425 77.575,10.425 77.575,0.575 77.25,0.25 67.825,0.25 64.25,0.25 62.925,1.575 62.925,8.725
VO on Signal Layer 1 "Top Layer-No Net 2" (solid, pour order 384): 51.325,9.875 51.5,9.7 69.617,9.7 70.7,11.375 70.7,14.5 66.75,14.5 65.275,13.025 52.325,13.025 51.325,12.025
VSW on Top Solder "Bottom Layer-No Net" (solid): 54.05,35.5 55.1,34.45 55.1,29.5 54.525,28.925 54.525,28.375 55.175,27.725 55.175,26.35 53.875,25.05 48.275,25.05 47.975,25.35 47.975,27.075 48.725,27.825 48.725,32.175 50.375,33.825 50.375,35.05 50.825,35.5

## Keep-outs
Keep-Out Layer:
  lines w0.254: 0,0 0,42 77.725,42 77.725,0 0,0
  lines w1.25: 45.9,11.275 48.2,13.575 65.2,13.575 66.9,15.275 66.9,38.45

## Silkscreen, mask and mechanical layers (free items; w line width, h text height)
Top Overlay:
  lines w0.2: 68.505,15.49 68.525,15.51
  text "CY" at 45.025,12.2 h0.4
Bottom Overlay:
  text "TIDA-01623-E1" at 7.15,18.6 h2.79 r90
Bottom Solder:
  region: 33.625,3.6 33.625,4.925 32.6,4.925 32.6,3.6
  rectangle: 30.775,10.725 32.1,11.75
Drill Guide:
  text ".Layer_Name" at 0.781,-22.456 h0.76
M1 Board Outline:
  lines w0.254: 0,-2.979 0,-2.471 ; 1.524,-3.233 0,-2.725 ; 1.524,-2.217 0,-2.725 ; 30.839,-2.725 0,-2.725 ; 46.886,-2.725 77.725,-2.725 ; 76.201,-3.233 77.725,-2.725 ; 76.201,-2.217 77.725,-2.725 ; 77.725,-2.979 77.725,-2.471 ; 82.067,1.524 82.575,0 ; 82.067,40.476 82.575,42 ; 82.321,0 82.829,0 ; 82.321,42 82.829,42 ; 82.575,15.896 82.575,0 ; 82.575,26.104 82.575,42 ; 83.083,1.524 82.575,0 ; 83.083,40.476 82.575,42 ; 0,0 77.725,0 77.725,42 0,42 0,0
  text "42 (mm)" at 83.489,16.15 h1.52 r90
  text "77.725 (mm)" at 31.093,-3.639 h1.52
  text ".Layer_Name" at 0.781,-22.456 h0.76
M2 Board Dimensions:
  text ".Layer_Name" at 0.781,-22.456 h0.76
M3 3D STEP Top:
  text ".Layer_Name" at 0.781,-22.456 h0.76
M4 3D STEP Bottom:
  text ".Layer_Name" at 0.781,-22.456 h0.76
M5 Assembly Top:
  lines w0.254: -21.292,-24.276 146.348,-24.276 ; -21.292,-19.112 146.399,-19.112 ; -21.292,-13.947 -21.292,-29.441 80.435,-29.441 146.399,-29.441 146.399,-13.947 -21.279,-13.947 -21.279,-29.441 18.739,-29.441 ; 41.319,-29.441 41.319,-13.947 ; 73.501,-19.112 73.501,-13.947 ; 94.837,-19.112 94.837,-13.947 ; 110.636,-29.606 110.636,-24.454
  text "PCB VIEWED FROM TOP SIDE" at -19.679,-17.304 h0.76
  text "BOARD #:" at 43.224,-17.304 h0.76
  text ".PRJ_Number" at 57.08,-17.304 h0.76
  text "REV:" at 78.53,-17.304 h0.76
  text ".PCB_Rev" at 85.934,-17.304 h0.76
  text "SVN REV:" at 99.815,-17.304 h0.76
  text ".VersionControl_RevNumber" at 112.668,-17.304 h0.76
  text "TID #:" at 43.224,-22.469 h0.76
  text ".TID" at 57.08,-22.469 h0.76
  text "PLOT NAME =" at -19.679,-27.684 h0.76
  text ".plot_File_Name" at 0.781,-27.684 h0.76
  text "GENERATED    :" at 43.275,-27.684 h0.76
  text ".Print_Date" at 65.36,-27.684 h0.76
  text ".Print_Time" at 83.877,-27.684 h0.76
  text "TEXAS INSTRUMENTS" at 115.995,-27.684 h0.76
M6 Assembly Bottom:
  lines w0.254: -21.305,-19.124 146.386,-19.124 ; -21.254,-24.289 146.386,-24.289 ; 14.459,-29.619 14.459,-24.467 ; 30.257,-19.124 30.257,-13.96 ; 51.593,-19.124 51.593,-13.96 ; 83.775,-29.454 83.775,-13.96 ; 106.356,-29.454 146.374,-29.454 146.374,-13.96 -21.305,-13.96 -21.305,-29.454 44.659,-29.454 146.386,-29.454 146.386,-13.96
  text ".VersionControl_RevNumber" at 12.427,-17.317 h0.76
  text "SVN REV:" at 25.279,-17.317 h0.76
  text ".PCB_Rev" at 39.16,-17.317 h0.76
  text "REV:" at 46.564,-17.317 h0.76
  text ".PRJ_Number" at 68.015,-17.317 h0.76
  text "BOARD #:" at 81.87,-17.317 h0.76
  text "PCB VIEWED FROM BOTTOM SIDE" at 144.773,-17.317 h0.76
  text ".TID" at 68.015,-22.481 h0.76
  text "TID #:" at 81.87,-22.481 h0.76
  text "TEXAS INSTRUMENTS" at 9.099,-27.697 h0.76
  text ".Print_Time" at 41.218,-27.697 h0.76
  text ".Print_Date" at 59.734,-27.697 h0.76
  text "GENERATED    :" at 81.819,-27.697 h0.76
  text ".plot_File_Name" at 124.314,-27.697 h0.76
  text "PLOT NAME =" at 144.773,-27.697 h0.76
M9 Title Sheet:
  drawing of 57 lines, arcs and shapes, not listed
  text "1" at 4.917,203.477 h0.76
  text "2" at 68.307,203.477 h0.76
  text "3" at 131.536,203.477 h0.76
  text "4" at 195.205,203.477 h0.76
  text "5" at 258.68,203.477 h0.76
  text "6" at 322.307,203.477 h0.76
  text "A" at -24.454,174.445 h0.76
  text "A" at 351.466,174.445 h0.76
  text "B" at -24.454,113.993 h0.76
  text "B" at 351.466,113.993 h0.76
  text "C" at -24.454,53.668 h0.76
  text "C" at 351.466,53.668 h0.76
  text "PROJECT TITLE:" at 274.25,6.399 h0.76
  text ".PRJ_Title" at 275.52,3.012 h0.76
  text "DESIGNED FOR:" at 274.25,-1.247 h0.76
  text ".PRJ_Customer" at 275.52,-4.803 h0.76
  text "D" at -24.454,-6.53 h0.76
  text "D" at 351.466,-6.53 h0.76
  text "FILE NAME:" at 274.25,-8.867 h0.76
  text ".PCB_File_Name_No_Path" at 275.52,-11.915 h0.76
  text "Texas Instruments (TI) and/or its licensors do not warrant the accuracy or completeness of this specification" at 148.025,-16.026 h0.76
  text "ENGINEER:" at 274.25,-16.233 h0.76
  text "LAYOUT BY:" at 312.477,-16.233 h0.76
  text "or any information contained therein. TI and/or its licensors do not warrant that this design will meet" at 146.882,-18.887 h0.76
  text ".PRJ_Engineer" at 275.52,-20.17 h0.76
  text ".PCB_Layout" at 313.76,-20.17 h0.76
  text "the specifications, will be suitable for your application or fit for any particular purpose, or will operate in" at 146.882,-21.749 h0.76
  text ".Layer_Name" at 0.781,-22.456 h0.76
  text "ALTIUM DESIGNER VERSION:" at 312.477,-24.107 h0.76
  text "an implementation. TI and/or its licensors do not warrant that the design is production worthy. You should" at 146.882,-24.611 h0.76
  text "completely validate and test your design implementation to confirm the system functionality for your application." at 148.025,-27.472 h0.76
  text ".print_Scale" at 275.52,-27.493 h0.76
  text ".Application_BuildNumber" at 313.76,-27.493 h0.76
  text "1" at 4.917,-32.743 h0.76
  text "2" at 68.307,-32.743 h0.76
  text "3" at 131.536,-32.743 h0.76
  text "4" at 195.205,-32.743 h0.76
  text "5" at 258.68,-32.743 h0.76
  text "6" at 322.307,-32.743 h0.76
M10 Fab Notes:
  drawing of 173 lines, arcs and shapes, not listed
  text "DESIGN INFORMATION" at 300.527,156.855 h0.76
  text "MIN. TRACK WIDTH:" at 284.155,152.283 h0.76
  text "8" at 311.999,152.283 h0.76
  text "MIL" at 315.93,152.283 h0.76
  text "MIN. CLEARANCE:" at 284.155,148.931 h0.76
  text "0.2" at 310.475,148.931 h0.76
  text "mm" at 315.93,148.931 h0.76
  text "MIN. VIA PAD SIZE:" at 284.155,145.578 h0.76
  text "24" at 311.238,145.578 h0.76
  text "MIL" at 315.93,145.578 h0.76
  text "0.05mm (2MIL)" at 301.808,141.978 h0.76
  text "MINIMUM ANNULAR RING" at 275.792,141.87 h0.76
  text "EXTERNAL" at 319.791,141.87 h0.76
  text "PER" at 280.872,138.872 h0.76
  text "IPC-D-275 CLASS 2 LEVEL C" at 286.46,138.872 h0.76
  text "MIL, HOLES" at 324.261,136.02 h0.76
  text "+/-" at 314.293,136.002 h0.76
  text "+/-" at 335.985,136.002 h0.76
  text "REGISTRATION TOLERANCES:" at 275.792,135.875 h0.76
  text "METAL" at 306.267,135.875 h0.76
  text "5" at 320.902,135.875 h0.76
  text "3" at 342.06,135.875 h0.76
  text "MIL" at 345.013,135.875 h0.76
  text "+/-" at 335.985,133.005 h0.76
  text "HOLE SIZE TOLERANCE (UNLESS OTHERWISE SPECIFIED):" at 275.792,132.878 h0.76
  text "3" at 342.06,132.878 h0.76
  text "MIL" at 345.013,132.878 h0.76
  text "MATERIAL:" at 273.893,127.558 h0.76
  text "FR-4 High Tg" at 298.949,123.993 h0.76
  text "FR-408" at 284.587,123.775 h0.76
  text "OTHER" at 322.382,123.775 h0.76
  text "X" at 295.014,123.683 h0.76
  text "62 MIL (1.6mm) +/-10%" at 292.717,119.642 h0.76
  text "THICKNESS:" at 275.792,119.534 h0.76
  text "X" at 289.462,119.534 h0.76
  text "OTHER" at 325.354,119.534 h0.76
  text "TOLERANCE:" at 275.792,115.52 h0.76
  text "X" at 297.111,115.52 h0.76
  text "ANSI IPC-6012 TYPE 3 CLASS 2" at 301.859,115.52 h0.76
  text "OTHER +/-" at 301.859,111.558 h0.76
  text "BOW & TWIST:" at 275.792,107.57 h0.76
  text "X" at 297.111,107.57 h0.76
  text "ANSI IPC-6012 TYPE 3 CLASS 2" at 301.859,107.57 h0.76
  text "OTHER +/-" at 301.859,103.544 h0.76
  text "DRILLING:" at 273.893,100.026 h0.76
  text "REFERENCE:" at 275.792,97.055 h0.76
  text "X" at 292.257,97.055 h0.76
  text "AS SHOWN" at 297.007,97.055 h0.76
  text "X" at 315.143,97.055 h0.76
  text "NC_DRILL FILES" at 318.623,97.055 h0.76
  text "PTH COPPER THICKNESS:" at 275.792,93.041 h0.76
  text "X" at 304.5,93.041 h0.76
  text "20-30 um" at 307.98,93.041 h0.76
  text "OTHER" at 326.192,93.041 h0.76
  text "BOARD FINISH:" at 273.893,89.003 h0.76
  text "SILKSCREEN:" at 277.836,86.006 h0.76
  text "X" at 301.935,86.006 h0.76
  text "TOP" at 305.135,86.006 h0.76
  text "X" at 314.889,86.006 h0.76
  text "BOTTOM" at 318.115,86.006 h0.76
  text "SILKSCREEN COLOR:" at 277.836,81.764 h0.76
  text "X" at 301.908,81.764 h0.76
  text "WHITE" at 305.135,81.764 h0.76
  text "OTHER" at 318.115,81.764 h0.76
  text "X" at 305.236,77.72 h0.76
  text "GREEN" at 308.463,77.72 h0.76
  text "OTHER" at 324.16,77.72 h0.76
  text "SOLDER RESIST COLOR:" at 277.836,77.446 h0.76
  text "X" at 305.236,73.402 h0.76
  text "MATTE" at 308.463,73.402 h0.76
  text "SEMI-GLOSS" at 324.148,73.386 h0.76
  text "IMMERSION GOLD (ENIG)" at 300.843,68.614 h0.76
  text "ENEPIG" at 334.816,68.53 h0.76
  text "SURFACE FINISH:" at 273.893,68.505 h0.76
  text "X" at 296.094,68.505 h0.76
  text "IMM. TIN/SILVER OR EQUIV" at 282.264,64.517 h0.76
  text "OTHER" at 318.623,64.517 h0.76
  text "ARRAY/PANEL:" at 273.893,59.971 h0.76
  text "CUT AND TRIM PER M1 BOARD OUTLINE" at 300.843,59.862 h0.76
  text "N.C. ROUTE" at 300.843,56.008 h0.76
  text "X" at 318.089,56.008 h0.76
  text "V. SCORE" at 322.839,56.008 h0.76
  text "CERTIFICATION:" at 273.893,52.528 h0.76
  text "MATERIALS AND WORKMANSHIP FOR ALL PCBS" at 292.308,52.528 h0.76
  text "TO MEET OR EXCEED THE REQUIREMENTS OF:" at 292.308,50.039 h0.76
  text "X" at 282.821,46.572 h0.76
  text "ANSI IPC-A-600F CLASS ->" at 286.352,46.572 h0.76
  text "X" at 327.984,46.572 h0.76
  text "2" at 331.005,46.572 h0.76
  text "1" at 323.004,46.534 h0.76
  text "3" at 339.997,46.534 h0.76
  text "X" at 303.498,42.521 h0.76
  text "RoHS" at 306.977,42.521 h0.76
  text "OTHER" at 323.345,42.521 h0.76
  text "PER ORDER" at 333.43,42.521 h0.76
  text "ALL BOARDS MUST MEET OR EXCEED UL94-V0 REQUIREMENTS." at 274.593,38.314 h0.76
  text "PCB MUST BEAR THE UL94V-0 UL REGISTERED MATERIAL ID NUMBER" at 274.593,35.266 h0.76
  text "ADDITIONAL REQUIREMENTS:" at 273.893,30.862 h0.76
  text "MICROSECTION:" at 275.792,27.941 h0.76
  text "YES" at 298.798,27.941 h0.76
  text "REQUIRED" at 320.68,23.975 h0.76
  text "BARE BOARD ELEC. TEST:" at 275.792,23.903 h0.76
  text "NONE" at 308.958,23.903 h0.76
  text "X" at 317.454,23.903 h0.76
  text "PER ORDER" at 335.717,23.903 h0.76
  text ".Layer_Name" at 0.781,-22.456 h0.76
M11 Gerber Information:
  lines w0.254: -21.292,-24.276 146.348,-24.276 ; -21.292,-19.112 146.399,-19.112 ; -21.292,-13.947 -21.292,-29.441 80.435,-29.441 146.399,-29.441 146.399,-13.947 -21.279,-13.947 -21.279,-29.441 18.739,-29.441 ; 41.319,-29.441 41.319,-13.947 ; 73.501,-19.112 73.501,-13.947 ; 94.837,-19.112 94.837,-13.947 ; 110.636,-29.606 110.636,-24.454
  text "ALL ARTWORK VIEWED FROM TOP SIDE" at -19.679,-17.304 h0.76
  text "BOARD #:" at 43.224,-17.304 h0.76
  text ".PRJ_Number" at 57.08,-17.304 h0.76
  text "REV:" at 78.53,-17.304 h0.76
  text ".PCB_Rev" at 85.934,-17.304 h0.76
  text "SVN REV:" at 99.815,-17.304 h0.76
  text ".VersionControl_RevNumber" at 112.668,-17.304 h0.76
  text "LAYER NAME =" at -19.679,-22.456 h0.76
  text "TID #:" at 43.224,-22.469 h0.76
  text ".TID" at 57.08,-22.469 h0.76
  text "PLOT NAME =" at -19.679,-27.684 h0.76
  text ".plot_File_Name" at 0.781,-27.684 h0.76
  text "GENERATED    :" at 43.275,-27.684 h0.76
  text ".Print_Date" at 65.36,-27.684 h0.76
  text ".Print_Time" at 83.877,-27.684 h0.76
  text "TEXAS INSTRUMENTS" at 115.995,-27.684 h0.76
M12 Stackup:
  drawing of 191 lines, arcs and shapes, not listed
  text "Board Layer Stack" at 247.178,225.283 h0.76
  text "Constant" at 254.669,225.283 h0.76
  text "Thickness" at 263.176,225.283 h0.76
  text "Material" at 274.349,225.283 h0.76
  text "Name" at 286.411,225.283 h0.76
  text "Layer" at 291.871,225.283 h0.76
  text "Top Overlay" at 286.411,223.759 h0.76
  text "1" at 291.871,223.759 h0.76
  text "3.5" at 254.669,222.235 h0.76
  text "0.40mil" at 263.176,222.235 h0.76
  text "Solder Resist" at 274.349,222.235 h0.76
  text "Top Solder" at 286.411,222.235 h0.76
  text "2" at 291.871,222.235 h0.76
  text "1.40mil" at 263.176,220.711 h0.76
  text "Copper" at 274.349,220.711 h0.76
  text "Top Layer" at 286.411,220.711 h0.76
  text "3" at 291.871,220.711 h0.76
  text "4.8" at 254.669,219.187 h0.76
  text "59.20mil" at 263.176,219.187 h0.76
  text "FR-4" at 274.349,219.187 h0.76
  text "Dielectric1" at 286.411,219.187 h0.76
  text "4" at 291.871,219.187 h0.76
  text "1.40mil" at 263.176,217.663 h0.76
  text "Copper" at 274.349,217.663 h0.76
  text "Bottom Layer" at 286.411,217.663 h0.76
  text "5" at 291.871,217.663 h0.76
  text "3.5" at 254.669,216.139 h0.76
  text "0.40mil" at 263.176,216.139 h0.76
  text "Solder Resist" at 274.349,216.139 h0.76
  text "Bottom Solder" at 286.411,216.139 h0.76
  text "6" at 291.871,216.139 h0.76
  text "Bottom Overlay" at 286.411,214.615 h0.76
  text "7" at 291.871,214.615 h0.76
  text ".Layer_Name" at 0.781,-22.456 h0.76
M13 Component Bodies Top:
  text ".Layer_Name" at 0.781,-22.456 h0.76
M14 Component Bodies Bottom:
  text ".Layer_Name" at 0.781,-22.456 h0.76
M15 Courtyards Top:
  text ".Layer_Name" at 0.781,-22.456 h0.76
M16 Courtyards Bottom:
  text ".Layer_Name" at 0.781,-22.456 h0.76
Drill Drawing:
  text ".Layer_Name" at 0.781,-22.456 h0.76
M17 Embedded Cavity:
  text ".Layer_Name" at 0.781,-22.456 h0.76
M18 Embedded Assembly:
  text ".Layer_Name" at 0.781,-22.456 h0.76
M19 Embedded Keepout:
  text ".Layer_Name" at 0.781,-22.456 h0.76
